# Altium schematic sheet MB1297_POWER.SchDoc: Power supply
size A4; Date: Not used; ApprovedBy: Not used; CheckedBy: Not used; Author: Not used; CompanyName: STMicroelectronics; DrawnBy: Not used; Engineer: Not used; Organization: Not used; Address1: Not used; Address2: Not used; Address3: Not used; Address4: Not used; DocumentNumber: Not used; Revision: Not used; SheetNumber: 9; SheetTotal: 12
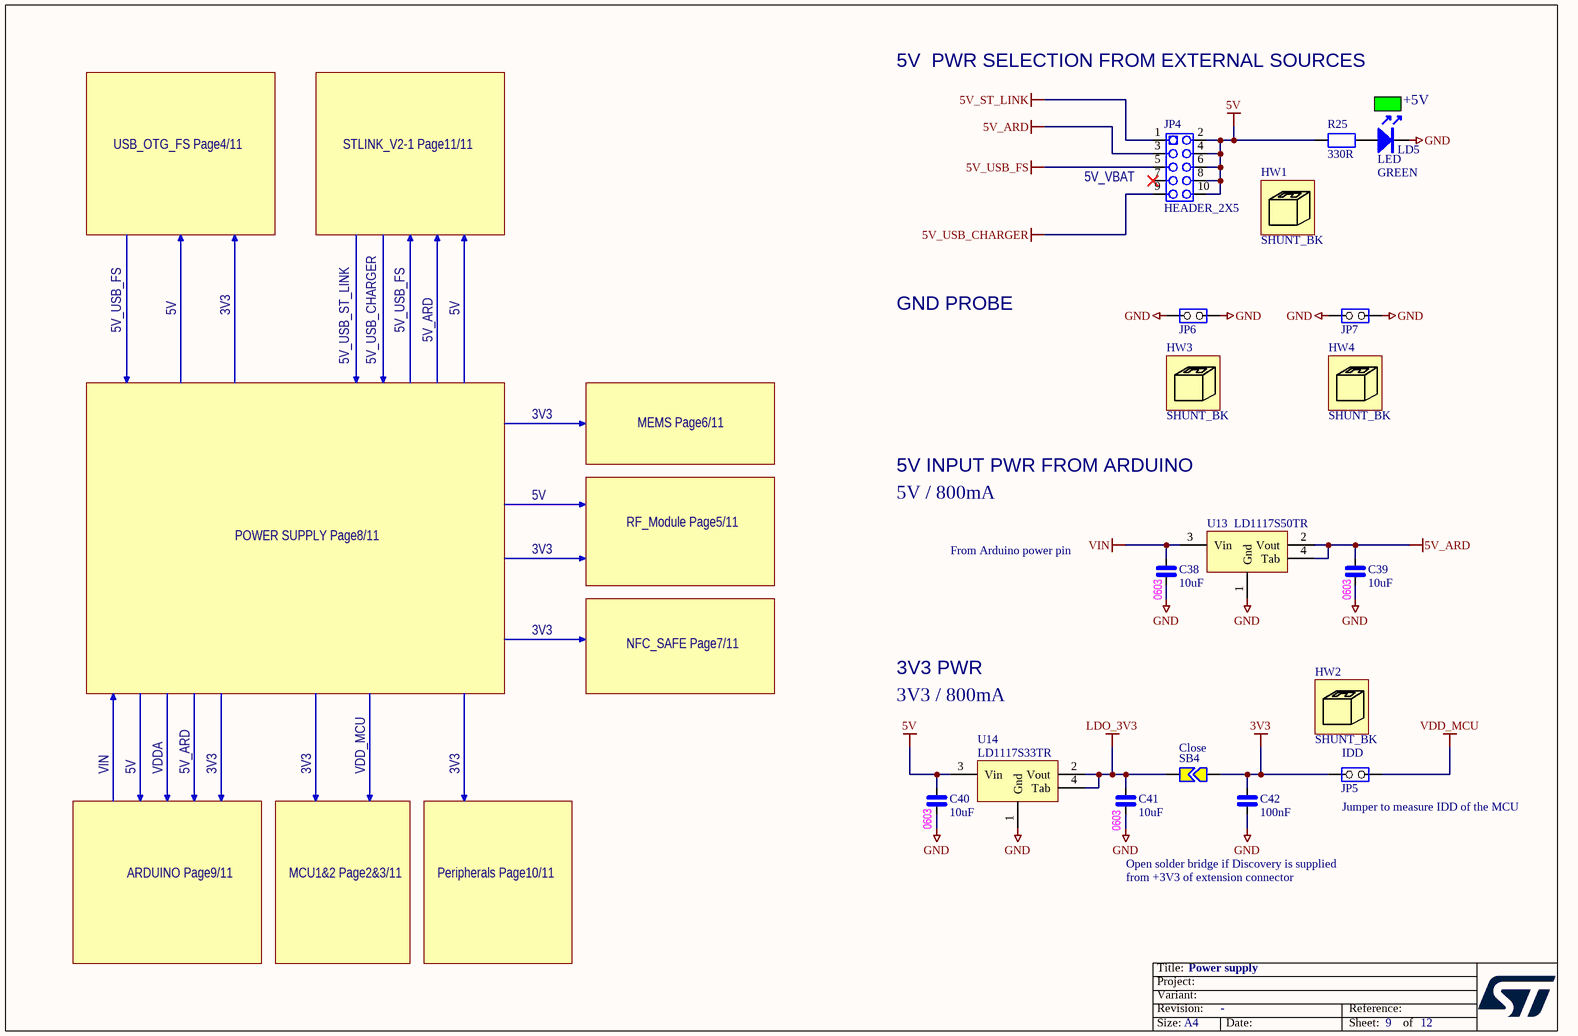
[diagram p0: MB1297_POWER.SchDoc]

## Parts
C38  10uF  [0603_CAP_NPOL]
C39  10uF  [0603_CAP_NPOL]
C40  10uF  [0603_CAP_NPOL]
C41  10uF  [0603_CAP_NPOL]
C42  100nF  [0402]
HW1  SHUNT_BK  (mechanical)
HW2  SHUNT_BK  (mechanical)
HW3  SHUNT_BK  (mechanical)
HW4  SHUNT_BK  (mechanical)
JP4  HEADER_2X5  [Header M 2x5x2.54 TH V]
JP5  Jumper_2.54mm  [CON_SAMTEC_TSW-102-07-G-S]  (value not drawn)
JP6  Jumper_2.54mm  [CON_SAMTEC_TSW-102-07-G-S]  (value not drawn)
JP7  Jumper_2.54mm  [CON_SAMTEC_TSW-102-07-G-S]  (value not drawn)
LD5  LED  Color: GREEN  [0603_LED_GREEN]
R25  330R  [0402]
SB4  Close  [SB]
U13  LD1117S50TR  [REG_SOT223-TAB]
U14  LD1117S33TR  [REG_SOT223-TAB]

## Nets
3V3: C42.1 JP5.1(COMMON) SB4.2
5V: C40.1 JP4.2 JP4.4 JP4.6 JP4.8 JP4.10 R25.1 U14.3(Vin)
5V_ARD: C39.1 JP4.3 U13.2(Vout) U13.4(Tab)
5V_ST_LINK: JP4.1
5V_USB_CHARGER: JP4.9
5V_USB_FS: JP4.5
GND: C38.2 C39.2 C40.2 C41.2 C42.2 JP6.1(COMMON) JP6.2(NO) JP7.1(COMMON) JP7.2(NO) LD5.K U13.1(Gnd) U14.1(Gnd)
LDO_3V3: C41.1 SB4.1 U14.2(Vout) U14.4(Tab)
VDD_MCU: JP5.2(NO)
VIN: C38.1 U13.3(Vin)
NetLD5_A: LD5.A R25.2

Not connected (* = marked no-connect by the designer): JP4 7*

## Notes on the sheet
- 5V  PWR SELECTION FROM EXTERNAL SOURCES
- (near LD5) +5V
- USB_OTG_FS Page4/11
- STLINK_V2-1 Page11/11
- (near JP4) 5V_VBAT
- 5V
- 3V3
- GND PROBE
- 5V_USB_FS
- 5V_USB_ST_LINK
- 5V_USB_CHARGER
- 5V_ARD
- MEMS Page6/11
- 5V / 800mA
- 5V INPUT PWR FROM ARDUINO
- POWER SUPPLY Page8/11
- RF_Module Page5/11
- From Arduino power pin
- NFC_SAFE Page7/11
- (near C38) 0603
- (near C39) 0603
- 3V3 / 800mA
- 3V3 PWR
- VIN
- VDDA
- VDD_MCU
- (near JP5) IDD
- (near C40) 0603
- (near C41) 0603
- (near JP5) Jumper to measure IDD of the MCU
- ARDUINO Page9/11
- MCU1&2 Page2&3/11
- Peripherals Page10/11
- Open solder bridge if Discovery is supplied
  from +3V3 of extension connector

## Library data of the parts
C38-C42 = CAP_NPOL: Capacitor_not polarized
HW1-HW4 = Shunt 2.54mm: SHUNT 2.54mm BLACK; Manuf_1: SAMTEC; Manuf_Part_1: SNT-100-BK-G; Fitted: Manually; Ordered_By: Subcon
JP5-JP7 = TSW-102-07-x-S: Connector jumper 1 position; Manuf_1: SAMTEC; Manuf_Part_2: 4711955140470; Manuf_2: KONTEC; Order_Code: 423-2841; Fitted: YES; Ordered_By: Subcon
LD5 = LED: Light-Emitting Diode
R25 = RES: Resistor
SB4 = Strap2: Solder Jumper; Solder: YES
U13 = LD1117S50TR: IC REG LDO 5V 0.8A SOT223; Manuf_1: STM; ECCN_US/EU: EAR99/NEC; Ref St: 9176133; Fitted: YES
U14 = LD1117S33TR: LOW DROP FIXED AND ADJUSTABLE POSITIVE VOLTAGE REGULATORS (3.3 Volts); Manuf_1: STM; ECCN_US/EU: EAR99/NEC; Fitted: YES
